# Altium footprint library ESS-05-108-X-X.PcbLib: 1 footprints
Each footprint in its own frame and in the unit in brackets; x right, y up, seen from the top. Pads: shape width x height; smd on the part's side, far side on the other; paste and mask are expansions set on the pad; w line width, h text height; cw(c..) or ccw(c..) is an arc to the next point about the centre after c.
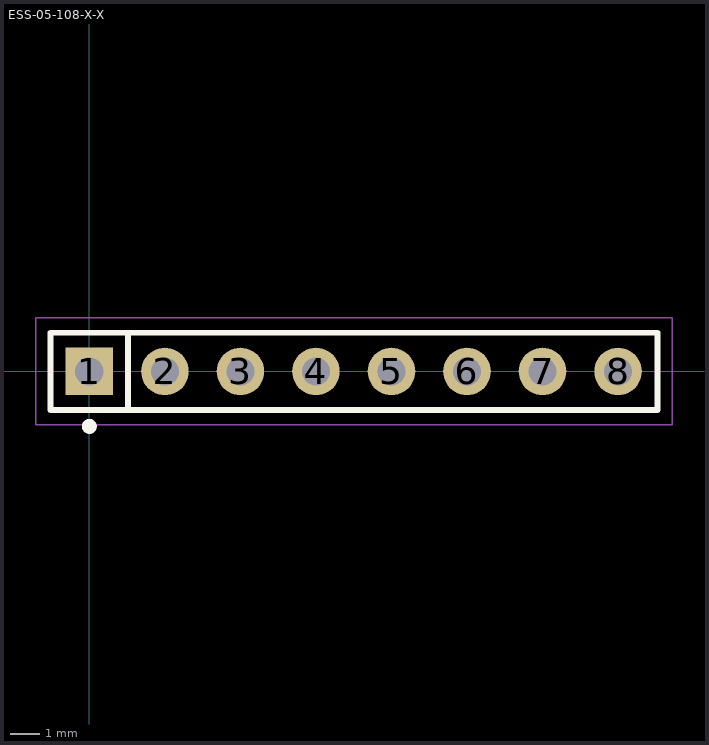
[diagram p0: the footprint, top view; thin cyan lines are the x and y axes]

## ESS-05-108-X-X [mm] "8 pin, single-in-line socket; w/strip header"
height 13.5
pads (8):
  rect 1.6x1.6 / inner round 1.6 / far side rect 1.6x1.6 hole 0.95 mask+0: 1(0,0)
  round 1.6 hole 0.95 mask+0: 2(2.54,0) 3(5.08,0) 4(7.62,0) 5(10.16,0) 6(12.7,0) 7(15.24,0) 8(17.78,0)
Top Overlay:
  circle w0.25: c0,-1.85 r0.125
  lines w0.2: 1.3,-1.3 1.3,1.3 ; -1.3,-1.3 19.1,-1.3 19.1,1.3 -1.3,1.3 -1.3,-1.3
Mechanical 12:
  lines w0.001: -1.3,-1.3 19.1,-1.3 19.1,1.3 -1.3,1.3 -1.3,-1.3
Mechanical 13:
  lines w0.1: -1.3,-1.3 19.1,-1.3 19.1,1.3 -1.3,1.3 -1.3,-1.3
  text ".Designator" at 0,0 h1.52
Mechanical 15:
  lines w0.05: -1.8,-1.8 19.6,-1.8 19.6,1.8 -1.8,1.8 -1.8,-1.8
